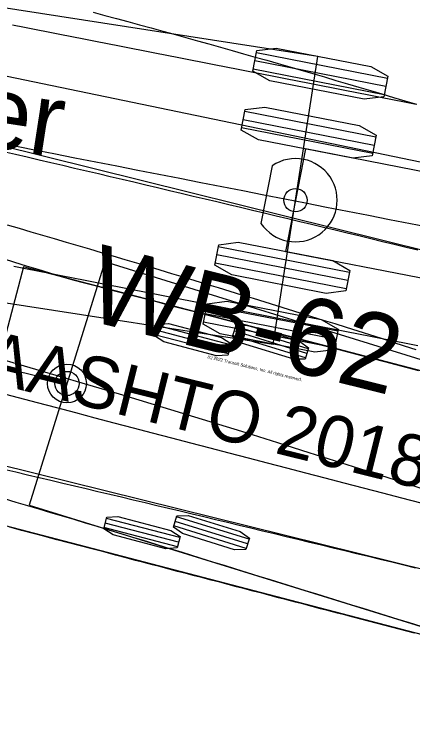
# Model space of a CAD drawing. Extents: x -14 to 1565148, y -25 to 642856.
# Drawn here: x 1565044.63 to 1565055.56, y 636485.05 to 636504.76 of the extents above; entities that cross this region are included whole.
import ezdxf

# ---------------------------------------------------------------- set-up
doc = ezdxf.new("R2010")
doc.units = 0
for name, color, linetype in [('DR_P_Headwall', 7, 'Continuous'), ('MT_P_Drums', 7, 'Continuous'), ('PM_P_Edge_Line', 7, 'Continuous'), ('TR_Turning_Path25', 7, 'Continuous'), ('TR_Turning_Path27', 7, 'Continuous'), ('TR_Turning_Path28 - Copy-1', 7, 'Continuous')]:
    doc.layers.add(name, color=color, linetype=linetype)

msp = doc.modelspace()

# ---------------------------------------------------------------- linework, layer by layer
at = {"layer": 'DR_P_Headwall'}
for p, q in [((1565047.11, 636497.956), (1565045.036, 636491.27)), ((1565065.257, 636492.328), (1565047.11, 636497.956)), ((1565052.655, 636495.44), (1565050.665, 636496.057)), ((1565052.694, 636495.564), (1565050.704, 636496.181)), ((1565052.616, 636495.316), (1565050.627, 636495.933)), ((1565046.073, 636494.613), (1565043.45, 636495.253)), ((1565046.073, 636494.613), (1565046.073, 636494.613)), ((1565045.036, 636491.27), (1565063.183, 636485.642)), ((1565051.07, 636490.331), (1565049.081, 636490.948)), ((1565050.993, 636490.082), (1565049.003, 636490.7)), ((1565051.032, 636490.207), (1565049.042, 636490.824))]:
    msp.add_line(p, q, dxfattribs=at)
for points in [[(1565044.436, 636498.97), (1565044.759, 636498.877), (1565045.081, 636498.783), (1565045.404, 636498.689), (1565045.726, 636498.595), (1565046.048, 636498.5), (1565046.37, 636498.406), (1565046.692, 636498.311), (1565047.014, 636498.215), (1565047.336, 636498.12), (1565047.658, 636498.024), (1565047.979, 636497.928), (1565048.3, 636497.832), (1565048.621, 636497.735), (1565048.942, 636497.638), (1565049.263, 636497.541), (1565049.584, 636497.444), (1565049.905, 636497.346), (1565050.225, 636497.249), (1565050.545, 636497.151), (1565050.865, 636497.052), (1565051.185, 636496.954), (1565051.505, 636496.855), (1565051.825, 636496.756), (1565052.144, 636496.657), (1565052.464, 636496.557), (1565052.783, 636496.457), (1565053.102, 636496.357), (1565053.421, 636496.257), (1565053.74, 636496.157), (1565054.058, 636496.056), (1565054.377, 636495.955), (1565054.695, 636495.854), (1565055.014, 636495.752), (1565055.332, 636495.65), (1565055.65, 636495.548)], [(1565055.794, 636487.934), (1565055.476, 636488.032), (1565055.159, 636488.13), (1565054.841, 636488.229), (1565054.525, 636488.327), (1565054.207, 636488.426), (1565053.889, 636488.525), (1565053.571, 636488.623), (1565053.253, 636488.722), (1565052.935, 636488.82), (1565052.617, 636488.919), (1565052.299, 636489.017), (1565051.982, 636489.116), (1565051.664, 636489.215), (1565051.346, 636489.313), (1565051.029, 636489.412), (1565050.711, 636489.51), (1565050.394, 636489.608), (1565050.076, 636489.707), (1565049.759, 636489.805), (1565049.442, 636489.904), (1565049.124, 636490.002), (1565048.807, 636490.1), (1565048.49, 636490.197), (1565048.172, 636490.295), (1565047.855, 636490.391), (1565047.537, 636490.488), (1565047.22, 636490.584), (1565046.902, 636490.681), (1565046.585, 636490.776), (1565046.267, 636490.872), (1565045.95, 636490.967), (1565045.632, 636491.062), (1565045.314, 636491.157), (1565044.997, 636491.251), (1565044.679, 636491.345), (1565044.361, 636491.439)]]:
    msp.add_lwpolyline(points, dxfattribs=at)
for points in [[(1565052.703, 636495.595), (1565052.607, 636495.285), (1565052.299, 636495.278), (1565050.867, 636495.722), (1565050.617, 636495.902), (1565050.713, 636496.212), (1565051.021, 636496.219), (1565052.454, 636495.775)], [(1565051.08, 636490.362), (1565050.984, 636490.052), (1565050.676, 636490.044), (1565049.243, 636490.489), (1565048.994, 636490.669), (1565049.09, 636490.979), (1565049.398, 636490.986), (1565050.83, 636490.542)]]:
    msp.add_lwpolyline(points, close=True, dxfattribs=at)
for radius in [0.533, 0.333]:
    msp.add_circle((1565046.073, 636494.613), radius, dxfattribs=at)
msp.add_arc((1564933.188, 636114.334), 396.808, 71.15589, 79.54898, dxfattribs=at)
at = {"layer": 'MT_P_Drums'}
for p, q in [((1565052.956, 636503.602), (1565017.377, 636509.092)), ((1565054.869, 636502.997), (1565051.271, 636503.702)), ((1565051.736, 636495.696), (1565052.956, 636503.602)), ((1565052.956, 636503.602), (1565052.956, 636503.602)), ((1565054.825, 636502.772), (1565051.227, 636503.477)), ((1565054.781, 636502.547), (1565051.183, 636503.252)), ((1565054.552, 636501.378), (1565050.954, 636502.083)), ((1565054.508, 636501.153), (1565050.91, 636501.858)), ((1565054.464, 636500.928), (1565050.866, 636501.633)), ((1565016.157, 636501.186), (1565051.736, 636495.696)), ((1565052.621, 636501.056), (1565052.07, 636498.242)), ((1565062.435, 636499.134), (1565052.621, 636501.056)), ((1565051.708, 636500.597), (1565051.397, 636499.011)), ((1565053.825, 636497.665), (1565050.227, 636498.37)), ((1565052.07, 636498.242), (1565061.884, 636496.321)), ((1565053.781, 636497.44), (1565050.183, 636498.145)), ((1565053.737, 636497.215), (1565050.139, 636497.92)), ((1565053.508, 636496.046), (1565049.91, 636496.75)), ((1565053.464, 636495.821), (1565049.866, 636496.526)), ((1565053.42, 636495.596), (1565049.822, 636496.301))]:
    msp.add_line(p, q, dxfattribs=at)
for points in [[(1565044.579, 636504.467), (1565044.905, 636504.402), (1565045.231, 636504.338), (1565045.557, 636504.274), (1565045.882, 636504.209), (1565046.208, 636504.145), (1565046.534, 636504.081), (1565046.86, 636504.017), (1565047.186, 636503.953), (1565047.512, 636503.889), (1565047.837, 636503.824), (1565048.163, 636503.76), (1565048.489, 636503.696), (1565048.815, 636503.632), (1565049.141, 636503.568), (1565049.467, 636503.504), (1565049.793, 636503.44), (1565050.118, 636503.376), (1565050.444, 636503.312), (1565050.77, 636503.248), (1565051.096, 636503.184), (1565051.422, 636503.12), (1565051.748, 636503.056), (1565052.074, 636502.993), (1565052.4, 636502.929), (1565052.726, 636502.865), (1565053.052, 636502.801), (1565053.377, 636502.737), (1565053.703, 636502.674), (1565054.029, 636502.61), (1565054.355, 636502.546), (1565054.681, 636502.482), (1565055.007, 636502.419), (1565055.333, 636502.355), (1565055.659, 636502.291)], [(1565044.611, 636497.835), (1565044.938, 636497.771), (1565045.264, 636497.706), (1565045.59, 636497.642), (1565045.916, 636497.578), (1565046.243, 636497.514), (1565046.569, 636497.449), (1565046.895, 636497.385), (1565047.221, 636497.321), (1565047.548, 636497.257), (1565047.874, 636497.193), (1565048.2, 636497.129), (1565048.527, 636497.064), (1565048.853, 636497), (1565049.179, 636496.936), (1565049.506, 636496.872), (1565049.832, 636496.808), (1565050.158, 636496.744), (1565050.484, 636496.68), (1565050.811, 636496.616), (1565051.137, 636496.552), (1565051.463, 636496.489), (1565051.79, 636496.425), (1565052.116, 636496.361), (1565052.442, 636496.297), (1565052.769, 636496.233), (1565053.095, 636496.169), (1565053.422, 636496.106), (1565053.748, 636496.042), (1565054.074, 636495.978), (1565054.401, 636495.914), (1565054.727, 636495.851), (1565055.053, 636495.787), (1565055.38, 636495.723), (1565055.706, 636495.66)]]:
    msp.add_lwpolyline(points, dxfattribs=at)
for points in [[(1565054.88, 636503.053), (1565054.77, 636502.492), (1565054.233, 636502.421), (1565051.643, 636502.928), (1565051.172, 636503.196), (1565051.282, 636503.758), (1565051.819, 636503.828), (1565054.41, 636503.321)], [(1565054.563, 636501.434), (1565054.453, 636500.872), (1565053.916, 636500.802), (1565051.326, 636501.309), (1565050.855, 636501.577), (1565050.965, 636502.138), (1565051.502, 636502.209), (1565054.093, 636501.702)], [(1565053.836, 636497.721), (1565053.726, 636497.16), (1565053.189, 636497.089), (1565050.599, 636497.596), (1565050.128, 636497.864), (1565050.238, 636498.425), (1565050.775, 636498.496), (1565053.366, 636497.989)], [(1565053.519, 636496.102), (1565053.409, 636495.54), (1565052.872, 636495.47), (1565050.282, 636495.977), (1565049.811, 636496.245), (1565049.921, 636496.806), (1565050.458, 636496.877), (1565053.049, 636496.369)]]:
    msp.add_lwpolyline(points, close=True, dxfattribs=at)
msp.add_circle((1565052.346, 636499.649), 0.32, dxfattribs=at)
for centre, radius, start, end in [((1566036.717, 641528.725), 5124.53, 258.665987, 259.085837), ((1565052.346, 636499.649), 1.143, 213.9219, 123.9219)]:
    msp.add_arc(centre, radius, start, end, dxfattribs=at)
at = {"layer": 'PM_P_Edge_Line'}
for p, q in [((1565044.877, 636497.819), (1565043.102, 636491.047)), ((1565063.256, 636492.999), (1565044.877, 636497.819)), ((1565050.561, 636495.677), (1565048.546, 636496.205)), ((1565050.528, 636495.551), (1565048.513, 636496.079)), ((1565050.495, 636495.425), (1565048.48, 636495.953)), ((1565043.102, 636491.047), (1565061.48, 636486.228)), ((1565049.172, 636490.377), (1565047.156, 636490.905)), ((1565049.138, 636490.251), (1565047.123, 636490.779)), ((1565049.105, 636490.125), (1565047.09, 636490.653))]:
    msp.add_line(p, q, dxfattribs=at)
for points in [[(1565044.319, 636498.047), (1565044.638, 636497.949), (1565044.957, 636497.85), (1565045.276, 636497.752), (1565045.595, 636497.653), (1565045.914, 636497.556), (1565046.235, 636497.465), (1565046.557, 636497.379), (1565046.88, 636497.294), (1565047.202, 636497.209), (1565047.525, 636497.125), (1565047.848, 636497.04), (1565048.17, 636496.955), (1565048.493, 636496.871), (1565048.816, 636496.786), (1565049.138, 636496.701), (1565049.461, 636496.617), (1565049.774, 636496.534), (1565050.087, 636496.452), (1565050.401, 636496.37), (1565050.714, 636496.288), (1565051.027, 636496.206), (1565051.34, 636496.124), (1565051.653, 636496.042), (1565051.967, 636495.96), (1565052.28, 636495.877), (1565052.593, 636495.795), (1565052.906, 636495.713), (1565053.22, 636495.631), (1565053.533, 636495.549), (1565053.846, 636495.467), (1565054.159, 636495.385), (1565054.472, 636495.303), (1565054.785, 636495.22), (1565055.098, 636495.138), (1565055.411, 636495.056), (1565055.724, 636494.974)], [(1565055.61, 636487.753), (1565055.4, 636487.808), (1565055.189, 636487.863), (1565054.979, 636487.918), (1565054.768, 636487.973), (1565054.558, 636488.028), (1565054.347, 636488.082), (1565054.137, 636488.137), (1565053.927, 636488.192), (1565053.726, 636488.244), (1565053.496, 636488.305), (1565053.265, 636488.365), (1565053.034, 636488.425), (1565052.803, 636488.485), (1565052.573, 636488.546), (1565052.342, 636488.606), (1565052.111, 636488.666), (1565051.88, 636488.726), (1565051.649, 636488.787), (1565051.419, 636488.847), (1565051.188, 636488.907), (1565050.957, 636488.968), (1565050.726, 636489.028), (1565050.495, 636489.089), (1565050.265, 636489.149), (1565050.034, 636489.209), (1565049.803, 636489.27), (1565049.572, 636489.33), (1565049.341, 636489.391), (1565049.111, 636489.451), (1565048.88, 636489.512), (1565048.649, 636489.572), (1565048.418, 636489.632), (1565048.187, 636489.693), (1565047.957, 636489.753), (1565047.726, 636489.814), (1565047.404, 636489.898), (1565047.081, 636489.983), (1565046.759, 636490.068), (1565046.437, 636490.152), (1565046.115, 636490.237), (1565045.793, 636490.321), (1565045.47, 636490.406), (1565045.148, 636490.491), (1565044.826, 636490.575), (1565044.504, 636490.663)]]:
    msp.add_lwpolyline(points, dxfattribs=at)
for points in [[(1565050.569, 636495.708), (1565050.487, 636495.393), (1565050.18, 636495.373), (1565048.729, 636495.753), (1565048.472, 636495.922), (1565048.554, 636496.236), (1565048.861, 636496.257), (1565050.312, 636495.876)], [(1565049.18, 636490.408), (1565049.097, 636490.093), (1565048.79, 636490.073), (1565047.339, 636490.453), (1565047.082, 636490.622), (1565047.164, 636490.936), (1565047.471, 636490.957), (1565048.922, 636490.576)]]:
    msp.add_lwpolyline(points, close=True, dxfattribs=at)
msp.add_arc((1566295.401, 641247.632), 4915.184, 255.233659, 255.436517, dxfattribs=at)
at = {"layer": 'TR_Turning_Path25'}
msp.add_line((1565024.726, 636507.152), (1565059.972, 636499.825), dxfattribs=at)
msp.add_lwpolyline([(1565046.794, 636504.814), (1565047.113, 636504.728), (1565047.43, 636504.642), (1565047.748, 636504.556), (1565048.066, 636504.469), (1565048.384, 636504.382), (1565048.701, 636504.295), (1565049.019, 636504.207), (1565049.336, 636504.119), (1565049.654, 636504.03), (1565049.971, 636503.942), (1565050.288, 636503.853), (1565050.605, 636503.763), (1565050.922, 636503.673), (1565051.239, 636503.583), (1565051.555, 636503.493), (1565051.872, 636503.402), (1565052.188, 636503.311), (1565052.505, 636503.219), (1565052.821, 636503.127), (1565053.137, 636503.035), (1565053.454, 636502.942), (1565053.77, 636502.85), (1565054.086, 636502.756), (1565054.401, 636502.663), (1565054.717, 636502.569), (1565055.033, 636502.475), (1565055.348, 636502.38), (1565055.664, 636502.285)], dxfattribs=at)
msp.add_arc((1564967.411, 636209.604), 308.945, 69.72175, 81.14322, dxfattribs=at)
at = {"layer": 'TR_Turning_Path27'}
msp.add_arc((1564828.253, 635754.783), 790.626, 70.211484, 74.167159, dxfattribs=at)
at = {"layer": 'TR_Turning_Path28 - Copy-1'}
for p, q in [((1565075.873, 636493.296), (1565029.355, 636504.843)), ((1565027.307, 636496.594), (1565073.825, 636485.046))]:
    msp.add_line(p, q, dxfattribs=at)
for points in [[(1565055.707, 636498.273), (1565055.382, 636498.351), (1565055.058, 636498.43), (1565054.733, 636498.509), (1565054.409, 636498.587), (1565054.084, 636498.666), (1565053.759, 636498.744), (1565053.435, 636498.822), (1565053.11, 636498.9), (1565052.785, 636498.978), (1565052.461, 636499.057), (1565052.136, 636499.134), (1565051.811, 636499.212), (1565051.486, 636499.29), (1565051.161, 636499.368), (1565050.837, 636499.445), (1565050.512, 636499.523), (1565050.187, 636499.6), (1565049.862, 636499.678), (1565049.537, 636499.755), (1565049.212, 636499.832), (1565048.887, 636499.909), (1565048.562, 636499.986), (1565048.236, 636500.063), (1565047.911, 636500.14), (1565047.586, 636500.217), (1565047.261, 636500.294), (1565046.936, 636500.37), (1565046.61, 636500.446), (1565046.285, 636500.523), (1565045.96, 636500.599), (1565045.634, 636500.675), (1565045.309, 636500.751), (1565044.983, 636500.827), (1565044.658, 636500.903), (1565044.332, 636500.979)], [(1565055.638, 636489.542), (1565055.315, 636489.62), (1565054.992, 636489.699), (1565054.669, 636489.777), (1565054.347, 636489.856), (1565054.024, 636489.934), (1565053.701, 636490.013), (1565053.379, 636490.091), (1565053.056, 636490.169), (1565052.733, 636490.247), (1565052.411, 636490.325), (1565052.088, 636490.403), (1565051.765, 636490.481), (1565051.443, 636490.559), (1565051.12, 636490.637), (1565050.797, 636490.714), (1565050.475, 636490.792), (1565050.152, 636490.869), (1565049.829, 636490.947), (1565049.506, 636491.024), (1565049.184, 636491.101), (1565048.861, 636491.178), (1565048.538, 636491.255), (1565048.216, 636491.332), (1565047.893, 636491.409), (1565047.57, 636491.486), (1565047.248, 636491.562), (1565046.925, 636491.639), (1565046.602, 636491.715), (1565046.28, 636491.792), (1565045.957, 636491.868), (1565045.634, 636491.944), (1565045.311, 636492.02), (1565044.989, 636492.096), (1565044.666, 636492.172), (1565044.343, 636492.248)]]:
    msp.add_lwpolyline(points, dxfattribs=at)

# ---------------------------------------------------------------- texts
at = {"layer": 'MT_P_Drums'}
msp.add_text('Gooseneck Horse Trailer', height=2, rotation=351.2276, dxfattribs=at).set_placement((1565016.462, 636505.348))
at = {"layer": 'TR_Turning_Path28 - Copy-1'}
for s, height, p in [('WB-62', 2.125, (1565046.509, 636496.381)), ('AASHTO 2018 (US)', 1.41667, (1565043.671, 636494.714)), ('(c) 2022 Transoft Solutions, Inc. All rights reserved.', 0.085, (1565049.925, 636495.314))]:
    msp.add_text(s, height=height, rotation=346.0586, dxfattribs=at).set_placement(p)

doc.saveas('drawing.dxf')
